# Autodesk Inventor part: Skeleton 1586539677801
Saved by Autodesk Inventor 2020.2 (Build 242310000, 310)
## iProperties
Created: 2020-04
Part Number: Skeleton 1586539677801
Material: Générique
Document SubType Name: Modeling
Designer: t.sancier
Density: 1 g/cm^3
Appearance: Par défaut
_SkeletonDoc: Frame Skeleton File
_Version: 15.0.0
Author: t.sancier
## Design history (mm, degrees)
sketch "Squelette de référence"
